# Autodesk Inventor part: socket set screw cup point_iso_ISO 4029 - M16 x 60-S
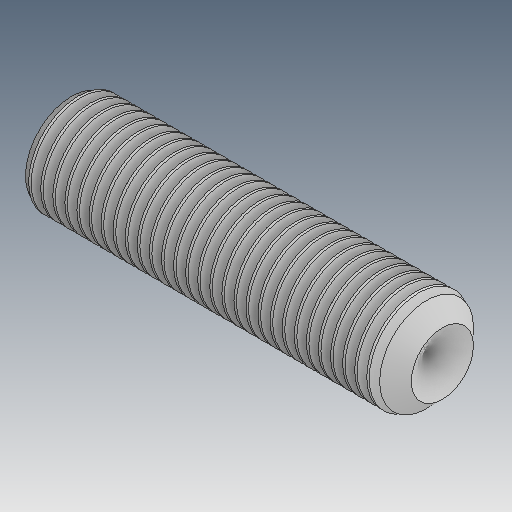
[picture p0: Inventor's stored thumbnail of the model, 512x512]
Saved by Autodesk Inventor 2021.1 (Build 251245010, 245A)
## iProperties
Created: 2019-04
Part Number: socket set screw cup point_iso_ISO 4029 - M16 x 60-S
Material: Ogólny
Document SubType Name: Modeling
Designer: user
Density: 1 g/cm^3
Appearance: Domyślna
Author: user
Revision Number: ÈÎºÎ
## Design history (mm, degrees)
feature "ÊäÈë1"
node "Bryła1"
